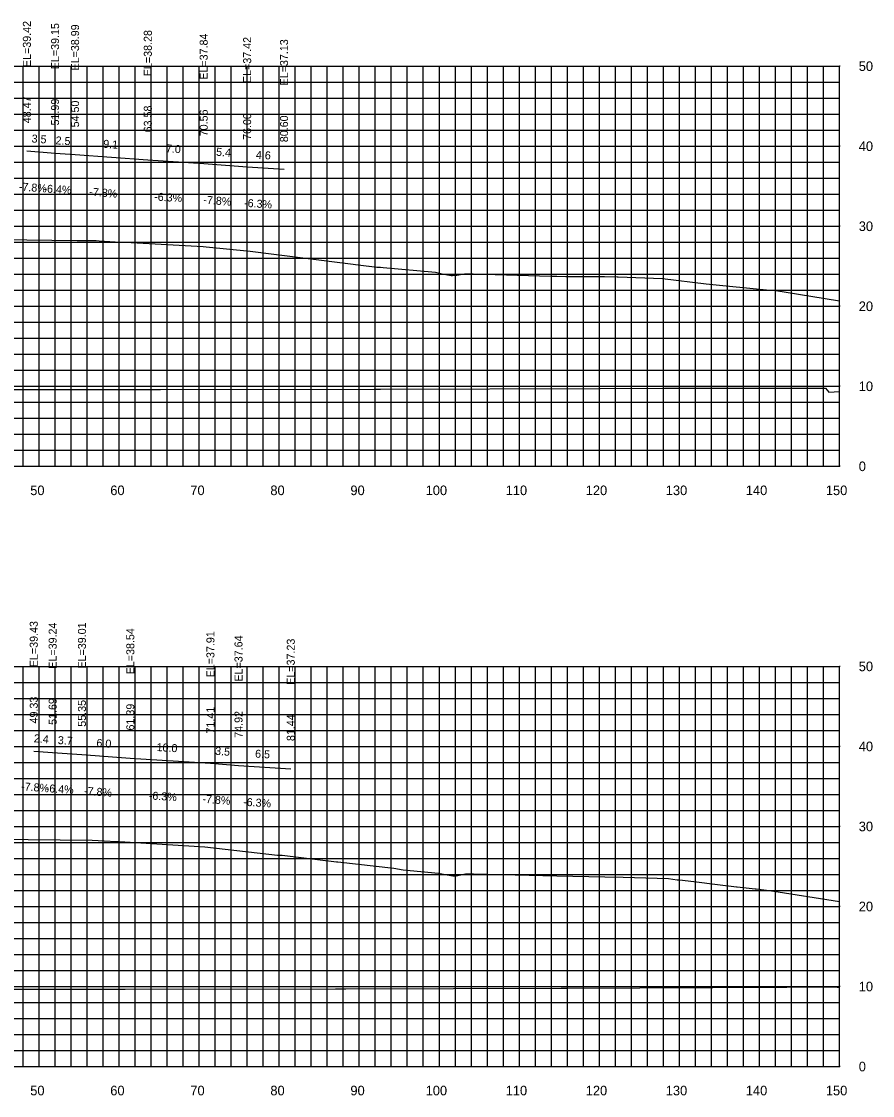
# Model space of a CAD drawing. Extents: x 1800880 to 1818864, y 245271 to 250560.
# Drawn here: x 1810136.3 to 1810242.6, y 249645.6 to 249779.8 of the extents above; entities that cross this region are included whole.
import ezdxf

# ---------------------------------------------------------------- set-up
doc = ezdxf.new("R2010")
doc.units = 0
for name, color, linetype in [('33', 7, 'Continuous'), ('ANNO-TXT', 7, 'Continuous'), ('CL-CNST', 7, 'Continuous'), ('DESIGN - DRAINAGE - Bridges', 7, 'Continuous'), ('Level 46', 7, 'Continuous'), ('Level 62', 7, 'Continuous'), ('SHT-BDR', 7, 'Continuous')]:
    doc.layers.add(name, color=color, linetype=linetype)

msp = doc.modelspace()

# ---------------------------------------------------------------- linework, layer by layer
at = {"layer": 'CL-CNST'}
for points in [[(1810133.78, 249752.55), (1810143.21, 249752.44), (1810145.58, 249752.42), (1810145.96, 249752.4), (1810148.63, 249752.25), (1810149.23, 249752.25), (1810158.96, 249751.67), (1810159.32, 249751.66), (1810164.82, 249751.11), (1810179.66, 249749.21), (1810179.69, 249749.21), (1810180.67, 249749.1), (1810181.1, 249749.1), (1810181.12, 249749.1), (1810181.43, 249749.08), (1810187.98, 249748.47), (1810188.65, 249748.33), (1810188.99, 249748.23), (1810189.02, 249748.23), (1810189.93, 249748.06), (1810190.12, 249748.06), (1810190.66, 249748.11), (1810191.61, 249748.28), (1810192.34, 249748.28), (1810192.39, 249748.28), (1810192.44, 249748.28), (1810192.49, 249748.28), (1810192.55, 249748.28), (1810192.61, 249748.28), (1810192.68, 249748.28), (1810192.69, 249748.28), (1810200.99, 249748.03), (1810202.38, 249747.99), (1810202.88, 249747.98), (1810203.13, 249747.97), (1810204.28, 249747.94), (1810204.4, 249747.94), (1810204.79, 249747.94), (1810204.98, 249747.94), (1810205.59, 249747.94), (1810209.09, 249747.93), (1810210.68, 249747.89), (1810210.81, 249747.89), (1810216.33, 249747.68), (1810221.78, 249747.02), (1810229.75, 249746.23), (1810229.98, 249746.24), (1810230.21, 249746.24), (1810231.55, 249746.02), (1810238.46, 249744.89)], [(1810133.36, 249677.67), (1810137.11, 249677.61), (1810145.09, 249677.5), (1810146.59, 249677.42), (1810148.14, 249677.33), (1810148.52, 249677.32), (1810159.15, 249676.68), (1810168.26, 249675.65), (1810168.51, 249675.65), (1810168.84, 249675.64), (1810175.61, 249674.78), (1810175.76, 249674.78), (1810182.76, 249674), (1810183.96, 249673.8), (1810188.37, 249673.39), (1810188.76, 249673.31), (1810188.96, 249673.25), (1810188.98, 249673.25), (1810190.13, 249673.04), (1810190.24, 249673.04), (1810190.56, 249673.07), (1810191.73, 249673.28), (1810192.64, 249673.28), (1810192.69, 249673.28), (1810192.73, 249673.28), (1810203.12, 249673.06), (1810209.12, 249672.92), (1810211.42, 249672.88), (1810217.11, 249672.72), (1810218.17, 249672.57), (1810218.46, 249672.57), (1810220.24, 249672.34), (1810223.23, 249671.97), (1810225.59, 249671.69), (1810225.68, 249671.69), (1810227.93, 249671.42), (1810227.93, 249671.42), (1810228.05, 249671.41), (1810229.94, 249671.19), (1810229.97, 249671.19), (1810230, 249671.19), (1810238.46, 249669.83)]]:
    msp.add_lwpolyline(points, dxfattribs=at)
at = {"layer": 'DESIGN - DRAINAGE - Bridges'}
for p, q in [((1810238.46, 249724.22), (1810238.46, 249774.22)), ((1810238.52, 249774.22), (1810238.46, 249774.22)), ((1810238.52, 249764.22), (1810238.46, 249764.22)), ((1810238.52, 249754.22), (1810238.46, 249754.22)), ((1810238.52, 249744.22), (1810238.46, 249744.22)), ((1810238.52, 249734.22), (1810238.46, 249734.22)), ((1809938.46, 249724.22), (1810238.46, 249724.22)), ((1810138.46, 249724.16), (1810138.46, 249724.22)), ((1810148.46, 249724.16), (1810148.46, 249724.22)), ((1810158.46, 249724.16), (1810158.46, 249724.22)), ((1810168.46, 249724.16), (1810168.46, 249724.22)), ((1810178.46, 249724.16), (1810178.46, 249724.22)), ((1810188.46, 249724.16), (1810188.46, 249724.22)), ((1810198.46, 249724.16), (1810198.46, 249724.22)), ((1810208.46, 249724.16), (1810208.46, 249724.22)), ((1810218.46, 249724.16), (1810218.46, 249724.22)), ((1810228.46, 249724.16), (1810228.46, 249724.22)), ((1810238.46, 249724.16), (1810238.46, 249724.22)), ((1810238.52, 249724.22), (1810238.46, 249724.22)), ((1810238.46, 249649.22), (1810238.46, 249699.22)), ((1810238.52, 249699.22), (1810238.46, 249699.22)), ((1810238.52, 249689.22), (1810238.46, 249689.22)), ((1810238.52, 249679.22), (1810238.46, 249679.22)), ((1810238.52, 249669.22), (1810238.46, 249669.22)), ((1810238.52, 249659.22), (1810238.46, 249659.22)), ((1809938.46, 249649.22), (1810238.46, 249649.22)), ((1810138.46, 249649.16), (1810138.46, 249649.22)), ((1810148.46, 249649.16), (1810148.46, 249649.22)), ((1810158.46, 249649.16), (1810158.46, 249649.22)), ((1810168.46, 249649.16), (1810168.46, 249649.22)), ((1810178.46, 249649.16), (1810178.46, 249649.22)), ((1810188.46, 249649.16), (1810188.46, 249649.22)), ((1810198.46, 249649.16), (1810198.46, 249649.22)), ((1810208.46, 249649.16), (1810208.46, 249649.22)), ((1810218.46, 249649.16), (1810218.46, 249649.22)), ((1810228.46, 249649.16), (1810228.46, 249649.22)), ((1810238.46, 249649.16), (1810238.46, 249649.22)), ((1810238.52, 249649.22), (1810238.46, 249649.22))]:
    msp.add_line(p, q, dxfattribs=at)
at = {"layer": 'Level 46'}
for p, q in [((1809938.46, 249774.22), (1810238.46, 249774.22)), ((1810136.46, 249724.22), (1810136.46, 249774.22)), ((1810138.46, 249724.22), (1810138.46, 249774.22)), ((1810140.46, 249724.22), (1810140.46, 249774.22)), ((1810142.46, 249724.22), (1810142.46, 249774.22)), ((1810144.46, 249724.22), (1810144.46, 249774.22)), ((1810146.46, 249724.22), (1810146.46, 249774.22)), ((1810148.46, 249724.22), (1810148.46, 249774.22)), ((1810150.46, 249724.22), (1810150.46, 249774.22)), ((1810152.46, 249724.22), (1810152.46, 249774.22)), ((1810154.46, 249724.22), (1810154.46, 249774.22)), ((1810156.46, 249724.22), (1810156.46, 249774.22)), ((1810158.46, 249724.22), (1810158.46, 249774.22)), ((1810160.46, 249724.22), (1810160.46, 249774.22)), ((1810162.46, 249724.22), (1810162.46, 249774.22)), ((1810164.46, 249724.22), (1810164.46, 249774.22)), ((1810166.46, 249724.22), (1810166.46, 249774.22)), ((1810168.46, 249724.22), (1810168.46, 249774.22)), ((1810170.46, 249724.22), (1810170.46, 249774.22)), ((1810172.46, 249724.22), (1810172.46, 249774.22)), ((1810174.46, 249724.22), (1810174.46, 249774.22)), ((1810176.46, 249724.22), (1810176.46, 249774.22)), ((1810178.46, 249724.22), (1810178.46, 249774.22)), ((1810180.46, 249724.22), (1810180.46, 249774.22)), ((1810182.46, 249724.22), (1810182.46, 249774.22)), ((1810184.46, 249724.22), (1810184.46, 249774.22)), ((1810186.46, 249724.22), (1810186.46, 249774.22)), ((1810188.46, 249724.22), (1810188.46, 249774.22)), ((1810190.46, 249724.22), (1810190.46, 249774.22)), ((1810192.46, 249724.22), (1810192.46, 249774.22)), ((1810194.46, 249724.22), (1810194.46, 249774.22)), ((1810196.46, 249724.22), (1810196.46, 249774.22)), ((1810198.46, 249724.22), (1810198.46, 249774.22)), ((1810200.46, 249724.22), (1810200.46, 249774.22)), ((1810202.46, 249724.22), (1810202.46, 249774.22)), ((1810204.46, 249724.22), (1810204.46, 249774.22)), ((1810206.46, 249724.22), (1810206.46, 249774.22)), ((1810208.46, 249724.22), (1810208.46, 249774.22)), ((1810210.46, 249724.22), (1810210.46, 249774.22)), ((1810212.46, 249724.22), (1810212.46, 249774.22)), ((1810214.46, 249724.22), (1810214.46, 249774.22)), ((1810216.46, 249724.22), (1810216.46, 249774.22)), ((1810218.46, 249724.22), (1810218.46, 249774.22)), ((1810220.46, 249724.22), (1810220.46, 249774.22)), ((1810222.46, 249724.22), (1810222.46, 249774.22)), ((1810224.46, 249724.22), (1810224.46, 249774.22)), ((1810226.46, 249724.22), (1810226.46, 249774.22)), ((1810228.46, 249724.22), (1810228.46, 249774.22)), ((1810230.46, 249724.22), (1810230.46, 249774.22)), ((1810232.46, 249724.22), (1810232.46, 249774.22)), ((1810234.46, 249724.22), (1810234.46, 249774.22)), ((1810236.46, 249724.22), (1810236.46, 249774.22)), ((1810238.46, 249724.22), (1810238.46, 249774.22)), ((1809938.46, 249772.22), (1810238.46, 249772.22)), ((1809938.46, 249770.22), (1810238.46, 249770.22)), ((1809938.46, 249768.22), (1810238.46, 249768.22)), ((1809938.46, 249766.22), (1810238.46, 249766.22)), ((1809938.46, 249764.22), (1810238.46, 249764.22)), ((1809938.46, 249762.22), (1810238.46, 249762.22)), ((1809938.46, 249760.22), (1810238.46, 249760.22)), ((1809938.46, 249758.22), (1810238.46, 249758.22)), ((1809938.46, 249756.22), (1810238.46, 249756.22)), ((1809938.46, 249754.22), (1810238.46, 249754.22)), ((1809938.46, 249752.22), (1810238.46, 249752.22)), ((1809938.46, 249750.22), (1810238.46, 249750.22)), ((1809938.46, 249748.22), (1810238.46, 249748.22)), ((1809938.46, 249746.22), (1810238.46, 249746.22)), ((1809938.46, 249744.22), (1810238.46, 249744.22)), ((1809938.46, 249742.22), (1810238.46, 249742.22)), ((1809938.46, 249740.22), (1810238.46, 249740.22)), ((1809938.46, 249738.22), (1810238.46, 249738.22)), ((1809938.46, 249736.22), (1810238.46, 249736.22)), ((1809938.46, 249734.22), (1810238.46, 249734.22)), ((1809938.46, 249732.22), (1810238.46, 249732.22)), ((1809938.46, 249730.22), (1810238.46, 249730.22)), ((1809938.46, 249728.22), (1810238.46, 249728.22)), ((1809938.46, 249726.22), (1810238.46, 249726.22)), ((1809938.46, 249724.22), (1810238.46, 249724.22)), ((1809938.46, 249699.22), (1810238.46, 249699.22)), ((1810136.46, 249649.22), (1810136.46, 249699.22)), ((1810138.46, 249649.22), (1810138.46, 249699.22)), ((1810140.46, 249649.22), (1810140.46, 249699.22)), ((1810142.46, 249649.22), (1810142.46, 249699.22)), ((1810144.46, 249649.22), (1810144.46, 249699.22)), ((1810146.46, 249649.22), (1810146.46, 249699.22)), ((1810148.46, 249649.22), (1810148.46, 249699.22)), ((1810150.46, 249649.22), (1810150.46, 249699.22)), ((1810152.46, 249649.22), (1810152.46, 249699.22)), ((1810154.46, 249649.22), (1810154.46, 249699.22)), ((1810156.46, 249649.22), (1810156.46, 249699.22)), ((1810158.46, 249649.22), (1810158.46, 249699.22)), ((1810160.46, 249649.22), (1810160.46, 249699.22)), ((1810162.46, 249649.22), (1810162.46, 249699.22)), ((1810164.46, 249649.22), (1810164.46, 249699.22)), ((1810166.46, 249649.22), (1810166.46, 249699.22)), ((1810168.46, 249649.22), (1810168.46, 249699.22)), ((1810170.46, 249649.22), (1810170.46, 249699.22)), ((1810172.46, 249649.22), (1810172.46, 249699.22)), ((1810174.46, 249649.22), (1810174.46, 249699.22)), ((1810176.46, 249649.22), (1810176.46, 249699.22)), ((1810178.46, 249649.22), (1810178.46, 249699.22)), ((1810180.46, 249649.22), (1810180.46, 249699.22)), ((1810182.46, 249649.22), (1810182.46, 249699.22)), ((1810184.46, 249649.22), (1810184.46, 249699.22)), ((1810186.46, 249649.22), (1810186.46, 249699.22)), ((1810188.46, 249649.22), (1810188.46, 249699.22)), ((1810190.46, 249649.22), (1810190.46, 249699.22)), ((1810192.46, 249649.22), (1810192.46, 249699.22)), ((1810194.46, 249649.22), (1810194.46, 249699.22)), ((1810196.46, 249649.22), (1810196.46, 249699.22)), ((1810198.46, 249649.22), (1810198.46, 249699.22)), ((1810200.46, 249649.22), (1810200.46, 249699.22)), ((1810202.46, 249649.22), (1810202.46, 249699.22)), ((1810204.46, 249649.22), (1810204.46, 249699.22)), ((1810206.46, 249649.22), (1810206.46, 249699.22)), ((1810208.46, 249649.22), (1810208.46, 249699.22)), ((1810210.46, 249649.22), (1810210.46, 249699.22)), ((1810212.46, 249649.22), (1810212.46, 249699.22)), ((1810214.46, 249649.22), (1810214.46, 249699.22)), ((1810216.46, 249649.22), (1810216.46, 249699.22)), ((1810218.46, 249649.22), (1810218.46, 249699.22)), ((1810220.46, 249649.22), (1810220.46, 249699.22)), ((1810222.46, 249649.22), (1810222.46, 249699.22)), ((1810224.46, 249649.22), (1810224.46, 249699.22)), ((1810226.46, 249649.22), (1810226.46, 249699.22)), ((1810228.46, 249649.22), (1810228.46, 249699.22)), ((1810230.46, 249649.22), (1810230.46, 249699.22)), ((1810232.46, 249649.22), (1810232.46, 249699.22)), ((1810234.46, 249649.22), (1810234.46, 249699.22)), ((1810236.46, 249649.22), (1810236.46, 249699.22)), ((1810238.46, 249649.22), (1810238.46, 249699.22)), ((1809938.46, 249697.22), (1810238.46, 249697.22)), ((1809938.46, 249695.22), (1810238.46, 249695.22)), ((1809938.46, 249693.22), (1810238.46, 249693.22)), ((1809938.46, 249691.22), (1810238.46, 249691.22)), ((1809938.46, 249689.22), (1810238.46, 249689.22)), ((1809938.46, 249687.22), (1810238.46, 249687.22)), ((1809938.46, 249685.22), (1810238.46, 249685.22)), ((1809938.46, 249683.22), (1810238.46, 249683.22)), ((1809938.46, 249681.22), (1810238.46, 249681.22)), ((1809938.46, 249679.22), (1810238.46, 249679.22)), ((1809938.46, 249677.22), (1810238.46, 249677.22)), ((1809938.46, 249675.22), (1810238.46, 249675.22)), ((1809938.46, 249673.22), (1810238.46, 249673.22)), ((1809938.46, 249671.22), (1810238.46, 249671.22)), ((1809938.46, 249669.22), (1810238.46, 249669.22)), ((1809938.46, 249667.22), (1810238.46, 249667.22)), ((1809938.46, 249665.22), (1810238.46, 249665.22)), ((1809938.46, 249663.22), (1810238.46, 249663.22)), ((1809938.46, 249661.22), (1810238.46, 249661.22)), ((1809938.46, 249659.22), (1810238.46, 249659.22)), ((1809938.46, 249657.22), (1810238.46, 249657.22)), ((1809938.46, 249655.22), (1810238.46, 249655.22)), ((1809938.46, 249653.22), (1810238.46, 249653.22)), ((1809938.46, 249651.22), (1810238.46, 249651.22)), ((1809938.46, 249649.22), (1810238.46, 249649.22))]:
    msp.add_line(p, q, dxfattribs=at)
at = {"layer": 'Level 62'}
for points in [[(1810136.93, 249763.64), (1810140.45, 249763.36), (1810142.95, 249763.2), (1810152.04, 249762.5), (1810159.02, 249762.06), (1810164.45, 249761.64), (1810169.06, 249761.35)], [(1810126.15, 249733.84), (1810152.16, 249733.84), (1810153.62, 249733.83), (1810180.33, 249733.88), (1810181.09, 249733.87), (1810208.4, 249733.96), (1810208.55, 249733.96), (1810216.58, 249734), (1810218.15, 249733.99), (1810218.99, 249733.98), (1810235.68, 249733.98), (1810235.89, 249733.98), (1810235.89, 249733.98), (1810235.9, 249733.98), (1810236.02, 249733.99), (1810236.68, 249733.99), (1810236.69, 249733.99), (1810236.7, 249733.98), (1810237.1, 249733.49), (1810238.46, 249733.55)], [(1810137.79, 249688.64), (1810140.15, 249688.46), (1810143.81, 249688.23), (1810149.85, 249687.76), (1810159.86, 249687.13), (1810163.37, 249686.85), (1810169.9, 249686.44)], [(1810121.67, 249658.9), (1810147.17, 249658.9), (1810149.22, 249658.88), (1810175.49, 249658.93), (1810176.77, 249658.92), (1810203.69, 249659.01), (1810204.33, 249659), (1810231.8, 249659.14), (1810231.88, 249659.14), (1810236.32, 249659.16), (1810238.16, 249659.15), (1810238.46, 249659.14)]]:
    msp.add_lwpolyline(points, dxfattribs=at)

# ---------------------------------------------------------------- texts
for s, p in [('50', (1810137.35, 249720.62)), ('60', (1810147.35, 249720.62)), ('70', (1810157.35, 249720.62)), ('80', (1810167.35, 249720.62)), ('90', (1810177.35, 249720.62)), ('100', (1810186.75, 249720.62)), ('110', (1810196.75, 249720.62)), ('120', (1810206.75, 249720.62)), ('130', (1810216.75, 249720.62)), ('140', (1810226.75, 249720.62)), ('150', (1810236.75, 249720.62)), ('50', (1810137.35, 249645.62)), ('60', (1810147.35, 249645.62)), ('70', (1810157.35, 249645.62)), ('80', (1810167.35, 249645.62)), ('90', (1810177.35, 249645.62)), ('100', (1810186.75, 249645.62)), ('110', (1810196.75, 249645.62)), ('120', (1810206.75, 249645.62)), ('130', (1810216.75, 249645.62)), ('140', (1810226.75, 249645.62)), ('150', (1810236.75, 249645.62))]:
    msp.add_text(s, height=1.2).set_placement(p)
at = {"layer": '33'}
for s, p in [('50', (1810240.86, 249773.62)), ('40', (1810240.86, 249763.62)), ('30', (1810240.86, 249753.62)), ('20', (1810240.86, 249743.62)), ('10', (1810240.86, 249733.62)), ('0', (1810240.86, 249723.62)), ('50', (1810240.86, 249698.62)), ('40', (1810240.86, 249688.62)), ('30', (1810240.86, 249678.62)), ('20', (1810240.86, 249668.62)), ('10', (1810240.86, 249658.62)), ('0', (1810240.86, 249648.62))]:
    msp.add_text(s, height=1.2, dxfattribs=at).set_placement(p)
at = {"layer": 'ANNO-TXT'}
for s, rotation, p in [('3.5', 355.5414, (1810137.49, 249764.7)), ('2.5', 356.3662, (1810140.49, 249764.46)), ('9.1', 355.5483, (1810146.43, 249764.04)), ('7.0', 356.3965, (1810154.28, 249763.46)), ('5.4', 355.5672, (1810160.54, 249763.04)), ('4.6', 356.4159, (1810165.52, 249762.67)), ('-7.8%', 355.5414, (1810135.9, 249758.7)), ('-6.4%', 356.3662, (1810138.98, 249758.45)), ('-7.8%', 355.5483, (1810144.7, 249758.05)), ('-6.3%', 356.3965, (1810152.81, 249757.44)), ('-7.8%', 355.5672, (1810158.95, 249757.05)), ('-6.3%', 356.4159, (1810164.04, 249756.65)), ('2.4', 355.5385, (1810137.77, 249689.75)), ('3.7', 356.363, (1810140.77, 249689.52)), ('6.0', 355.5447, (1810145.59, 249689.19)), ('10.0', 356.3916, (1810153.11, 249688.65)), ('3.5', 355.5618, (1810160.42, 249688.18)), ('6.5', 356.4099, (1810165.42, 249687.83)), ('-7.8%', 355.5385, (1810136.18, 249683.75)), ('-6.4%', 356.363, (1810139.26, 249683.51)), ('-7.8%', 355.5447, (1810144.04, 249683.19)), ('-6.3%', 356.3916, (1810152.14, 249682.6)), ('-7.8%', 355.5618, (1810158.83, 249682.19)), ('-6.3%', 356.4099, (1810163.92, 249681.81))]:
    msp.add_text(s, height=1, rotation=rotation, dxfattribs=at).set_placement(p)
at = {"layer": 'SHT-BDR'}
for s, p in [('EL=39.42', (1810137.43, 249774.11)), ('EL=39.15', (1810140.95, 249773.84)), ('EL=38.99', (1810143.45, 249773.68)), ('EL=38.28', (1810152.54, 249772.97)), ('EL=37.84', (1810159.52, 249772.53)), ('EL=37.42', (1810164.95, 249772.11)), ('EL=37.13', (1810169.56, 249771.82)), ('48.47', (1810137.43, 249767.09)), ('51.99', (1810140.95, 249766.81)), ('54.50', (1810143.45, 249766.57)), ('63.58', (1810152.54, 249765.95)), ('70.56', (1810159.52, 249765.46)), ('76.00', (1810164.95, 249765.01)), ('80.60', (1810169.56, 249764.72)), ('EL=39.43', (1810138.29, 249699.12)), ('EL=39.24', (1810140.65, 249698.93)), ('EL=39.01', (1810144.31, 249698.95)), ('EL=38.54', (1810150.35, 249698.23)), ('EL=37.91', (1810160.36, 249697.85)), ('EL=37.64', (1810163.87, 249697.32)), ('EL=37.23', (1810170.4, 249696.92)), ('49.33', (1810138.29, 249692.09)), ('51.69', (1810140.65, 249691.91)), ('55.35', (1810144.31, 249691.68)), ('61.39', (1810150.35, 249691.21)), ('71.41', (1810160.36, 249690.83)), ('74.92', (1810163.87, 249690.3)), ('81.44', (1810170.4, 249689.89))]:
    msp.add_text(s, height=1, rotation=90, dxfattribs=at).set_placement(p)

doc.saveas('drawing.dxf')
